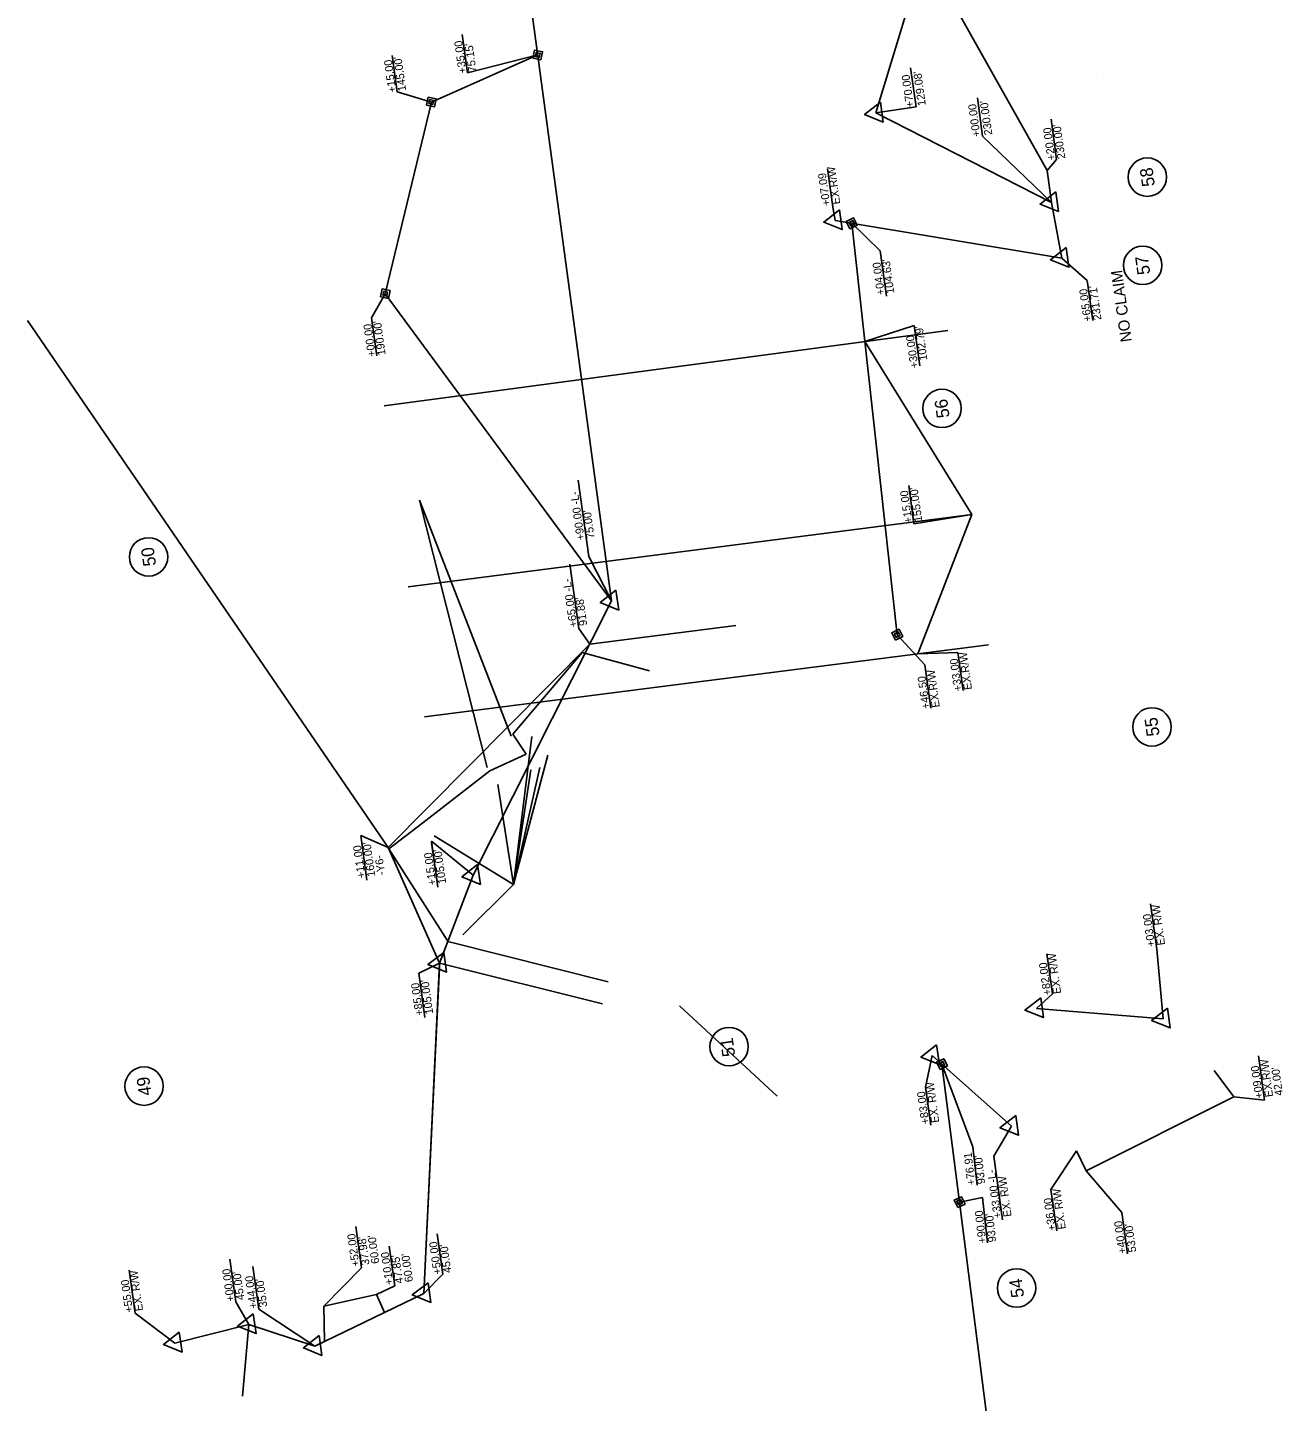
# Model space of a CAD drawing. Extents: x 474184 to 481900, y 489262 to 505659.
# Drawn here: x 477622 to 478406, y 497189 to 498047 of the extents above; entities that cross this region are included whole.
import ezdxf

# ---------------------------------------------------------------- set-up
doc = ezdxf.new("R2010")
doc.units = 0
for name, color, linetype in [('Prop Drainage Structure Box Number Symbol CELL', 7, 'Continuous'), ('Prop Drainage Structure Drop Inlet Grate 2 Wide Slots and Sag Grates 840 22 CELL', 7, 'Continuous'), ('Prop Drainage Structure Outlet Berm Ditch 850 10 Label', 7, 'Continuous'), ('Prop Drainage Structure Pipe CSP 15in', 7, 'Continuous'), ('Prop Drainage Structure Pipe Plug CELL', 7, 'Continuous'), ('Prop Drainage Structure Pipe RCP 18in Class IV', 7, 'Continuous'), ('Prop Drainage Structure Pipe RCP 18in Class IV Label', 7, 'Continuous'), ('Prop Drainage Structure Pipe Side Drain 15in Label', 7, 'Continuous'), ('Prop Drainage Structure Pipe Stub Out CELL', 7, 'Continuous'), ('Prop Drainage Structure Plot Symbol 50 Scale', 7, 'Continuous'), ('Prop Earthen Structure Base Ditch Lateral Detail Label', 7, 'Continuous'), ('Prop Earthen Structure False Sump CELL', 7, 'Continuous'), ('Prop Earthen Structure False Sump Label', 7, 'Continuous'), ('Sheet Block Title CELL', 7, 'Continuous'), ('Sheet Plot Border Outside CELL', 7, 'Continuous')]:
    doc.layers.add(name, color=color, linetype=linetype)

msp = doc.modelspace()

# ---------------------------------------------------------------- linework, layer by layer
at = {"layer": 'Prop Drainage Structure Box Number Symbol CELL'}
msp.add_line((478090.16, 497379.52), (478029.28, 497436.03), dxfattribs=at)
at = {"layer": 'Prop Drainage Structure Drop Inlet Grate 2 Wide Slots and Sag Grates 840 22 CELL'}
for p, q in [((477874.31, 498000.53), (477940.73, 498029.97)), ((477845.49, 497880.8), (477874.31, 498000.53)), ((477986.87, 497688.92), (477845.49, 497880.8))]:
    msp.add_line(p, q, dxfattribs=at)
at = {"layer": 'Prop Drainage Structure Outlet Berm Ditch 850 10 Label'}
for p, q in [((478165.24, 497667.84), (478136.84, 497924.8)), ((478204.16, 497313.42), (478193.15, 497399.62)), ((478260.5, 496872), (478204.16, 497313.42))]:
    msp.add_line(p, q, dxfattribs=at)
at = {"layer": 'Prop Drainage Structure Pipe CSP 15in'}
for p, q in [((478321.41, 497953.63), (478321.41, 497953.63)), ((478318.52, 497898.55), (478318.52, 497898.55)), ((478193.19, 497809.15), (478193.19, 497809.15)), ((477697.68, 497716.44), (477697.68, 497716.44)), ((478324.33, 497610.23), (478324.33, 497610.23)), ((478060.24, 497410.58), (478060.24, 497410.58)), ((477694.87, 497385.86), (477694.87, 497385.86)), ((478239.77, 497259.78), (478239.77, 497259.78))]:
    msp.add_line(p, q, dxfattribs=at)
for centre in [(478321.41, 497953.63), (478318.52, 497898.55), (478193.19, 497809.15), (477697.68, 497716.44), (478324.33, 497610.23), (478060.24, 497410.58), (477694.87, 497385.86), (478239.77, 497259.78)]:
    msp.add_circle(centre, 12, dxfattribs=at)
at = {"layer": 'Prop Drainage Structure Pipe RCP 18in Class IV'}
for p, q in [((477940.73, 498029.97), (477940.73, 498029.97)), ((477874.31, 498000.53), (477874.31, 498000.53)), ((478151.97, 497993.74), (478151.97, 497993.74)), ((478261.6, 497937.84), (478261.6, 497937.84)), ((478126.49, 497926.51), (478126.49, 497926.51)), ((478136.84, 497924.8), (478136.84, 497924.8)), ((478268.07, 497903.03), (478268.07, 497903.03)), ((477845.49, 497880.8), (477845.49, 497880.8)), ((477986.86, 497688.92), (477986.86, 497688.92)), ((478165.24, 497667.84), (478165.24, 497667.84)), ((477900.49, 497517.57), (477900.49, 497517.57)), ((477879.32, 497462.76), (477879.32, 497462.76)), ((478252.13, 497434.35), (478252.13, 497434.35)), ((478331.24, 497427.91), (478331.24, 497427.91)), ((478187.13, 497405), (478187.13, 497405)), ((478193.15, 497399.62), (478193.15, 497399.62)), ((478236.53, 497360.9), (478236.53, 497360.9)), ((478204.16, 497313.42), (478204.16, 497313.42)), ((477869.55, 497256.44), (477869.55, 497256.44)), ((477760.36, 497236.95), (477760.36, 497236.95)), ((477714.16, 497225.41), (477714.16, 497225.41)), ((477801.51, 497223.4), (477801.51, 497223.4))]:
    msp.add_line(p, q, dxfattribs=at)
for points in [[(478154.69, 498000.42), (478156.4, 497988.06), (478144.83, 497992.73)], [(478264.31, 497944.53), (478266.03, 497932.17), (478254.45, 497936.84)], [(478129.21, 497933.2), (478130.92, 497920.84), (478119.35, 497925.51)], [(478270.78, 497909.71), (478272.5, 497897.35), (478260.93, 497902.02)], [(477989.57, 497695.61), (477991.29, 497683.25), (477979.72, 497687.92)], [(477903.2, 497524.26), (477904.92, 497511.9), (477893.35, 497516.57)], [(477882.03, 497469.44), (477883.75, 497457.08), (477872.18, 497461.75)], [(478254.84, 497441.03), (478256.56, 497428.67), (478244.98, 497433.35)], [(478333.96, 497434.6), (478335.67, 497422.24), (478324.1, 497426.91)], [(478189.84, 497411.68), (478191.56, 497399.32), (478179.99, 497403.99)], [(478239.25, 497367.58), (478240.96, 497355.22), (478229.39, 497359.89)], [(477872.27, 497263.12), (477873.98, 497250.76), (477862.41, 497255.43)], [(477763.07, 497243.64), (477764.79, 497231.28), (477753.22, 497235.95)], [(477716.87, 497232.1), (477718.58, 497219.74), (477707.01, 497224.41)], [(477804.23, 497230.08), (477805.94, 497217.72), (477794.37, 497222.39)]]:
    msp.add_lwpolyline(points, close=True, dxfattribs=at)
at = {"layer": 'Prop Drainage Structure Pipe RCP 18in Class IV Label'}
for points in [[(477937.7, 498028.02), (477938.79, 498033), (477943.76, 498031.91), (477942.68, 498026.94)], [(477939.22, 498028.99), (477939.76, 498031.48), (477942.25, 498030.94), (477941.7, 498028.45)], [(477871.28, 497998.59), (477872.36, 498003.56), (477877.34, 498002.47), (477876.25, 497997.5)], [(477872.79, 497999.56), (477873.33, 498002.04), (477875.82, 498001.5), (477875.28, 497999.01)], [(478135.67, 497921.39), (478133.43, 497925.97), (478138.01, 497928.2), (478140.24, 497923.63)], [(478136.25, 497923.1), (478135.14, 497925.38), (478137.42, 497926.5), (478138.54, 497924.21)], [(477842.46, 497878.86), (477843.54, 497883.83), (477848.52, 497882.75), (477847.43, 497877.77)], [(477843.97, 497879.83), (477844.52, 497882.32), (477847, 497881.78), (477846.46, 497879.29)], [(478164.07, 497664.44), (478161.84, 497669.01), (478166.41, 497671.24), (478168.65, 497666.67)], [(478164.66, 497666.14), (478163.54, 497668.43), (478165.83, 497669.54), (478166.94, 497667.26)], [(478191.98, 497396.22), (478189.75, 497400.79), (478194.32, 497403.02), (478196.56, 497398.45)], [(478192.57, 497397.92), (478191.45, 497400.21), (478193.74, 497401.32), (478194.85, 497399.04)], [(478202.98, 497310.01), (478200.75, 497314.59), (478205.33, 497316.82), (478207.56, 497312.24)], [(478203.57, 497311.71), (478202.45, 497314), (478204.74, 497315.12), (478205.86, 497312.83)]]:
    msp.add_lwpolyline(points, close=True, dxfattribs=at)
at = {"layer": 'Prop Drainage Structure Pipe Side Drain 15in Label'}
for p, q in [((478151.97, 497993.74), (478182.38, 498093.88)), ((477986.86, 497688.92), (477935.51, 498068.61)), ((478261.6, 497937.84), (478151.97, 497993.74)), ((478268.07, 497903.03), (478261.6, 497937.84)), ((478268.07, 497903.03), (478126.49, 497926.51)), ((477900.49, 497517.57), (477986.86, 497688.92)), ((477879.32, 497462.76), (477900.49, 497517.57)), ((477869.55, 497256.44), (477879.32, 497462.76)), ((478331.24, 497427.91), (478252.13, 497434.35)), ((478236.53, 497360.9), (478187.13, 497405)), ((477801.51, 497223.4), (477869.55, 497256.44)), ((477714.16, 497225.41), (477760.36, 497236.95)), ((477760.36, 497236.95), (477801.51, 497223.4))]:
    msp.add_line(p, q, dxfattribs=at)
at = {"layer": 'Prop Drainage Structure Pipe Stub Out CELL'}
for p, q in [((478258.84, 497957.86), (478182.38, 498093.88)), ((478293.82, 498017.59), (478293.82, 498017.59)), ((478261.6, 497937.84), (478258.84, 497957.86)), ((478211.82, 497742.98), (478145.01, 497850.88)), ((478178.17, 497655.88), (478211.82, 497742.98)), ((477847.3, 497534.87), (477973.28, 497661.99)), ((477879.32, 497462.76), (477847.3, 497534.87)), ((478363.15, 497395.66), (478375.46, 497379.21)), ((478283.3, 497333.07), (478375.46, 497379.21)), ((478283.3, 497333.07), (478277.26, 497345.54)), ((477807.13, 497248.34), (477840.11, 497255.64)), ((477845.04, 497244.53), (477840.11, 497255.64)), ((477807.53, 497226.32), (477807.13, 497248.34))]:
    msp.add_line(p, q, dxfattribs=at)
at = {"layer": 'Prop Drainage Structure Plot Symbol 50 Scale'}
for p, q in [((478173.61, 498021.96), (478177.01, 497997.54)), ((478215.27, 498003.15), (478218.59, 497979.24)), ((478121.74, 497958.86), (478125.24, 497933.7)), ((478268.07, 497903.03), (478283.83, 497889.15)), ((478283.83, 497889.15), (478287.33, 497863.99)), ((477965.99, 497764.27), (477972.6, 497716.78)), ((477986.86, 497688.92), (477972.6, 497716.78)), ((477874.31, 497538.97), (477878.32, 497510.14)), ((477874.31, 497538.97), (477900.49, 497517.57)), ((477874.46, 497537.88), (477878.32, 497510.14)), ((478323.35, 497499.75), (478327.28, 497471.51)), ((478258.74, 497468.46), (478262.2, 497443.58)), ((477866.39, 497456.45), (477879.32, 497462.76)), ((477866.39, 497456.45), (477870.25, 497428.71)), ((477866.39, 497456.45), (477870.25, 497428.71)), ((478182.97, 497385.32), (478186.28, 497361.5)), ((478225.55, 497342.13), (478236.53, 497360.9)), ((478225.55, 497342.13), (478231.08, 497302.4)), ((477877.86, 497293.65), (477881.37, 497268.47)), ((477748.47, 497277.7), (477752.18, 497251.05)), ((477685.51, 497271), (477689.27, 497244.01)), ((477762.74, 497273.3), (477766.45, 497246.65)), ((477881.37, 497268.47), (477869.55, 497256.44)), ((477760.36, 497236.95), (477752.18, 497251.05)), ((477801.51, 497223.4), (477766.45, 497246.65))]:
    msp.add_line(p, q, dxfattribs=at)
for points in [[(478177.01, 497997.54), (478151.97, 497993.74)], [(478218.59, 497979.24), (478261.6, 497937.84)], [(478125.24, 497933.7), (478126.49, 497926.51)], [(478327.28, 497471.51), (478331.24, 497427.91)], [(478262.2, 497443.58), (478252.13, 497434.35)], [(478182.97, 497385.32), (478187.13, 497405)], [(477689.27, 497244.01), (477714.16, 497225.41)]]:
    msp.add_lwpolyline(points, dxfattribs=at)
at = {"layer": 'Prop Earthen Structure Base Ditch Lateral Detail Label'}
for p, q in [((478154.53, 497907.54), (478136.84, 497924.8)), ((478154.53, 497907.54), (478158.46, 497879.29)), ((478182.48, 497649.08), (478165.24, 497667.84)), ((478182.48, 497649.08), (478186.27, 497621.88)), ((478193.15, 497399.62), (478212.35, 497347.93)), ((478212.35, 497347.93), (478215.1, 497324.04)), ((478204.16, 497313.42), (478218.41, 497316.35)), ((478218.41, 497316.35), (478221.68, 497287.96))]:
    msp.add_line(p, q, dxfattribs=at)
at = {"layer": 'Prop Earthen Structure False Sump CELL'}
for p, q in [((477893.61, 498042.64), (477896.92, 498018.82)), ((477849.87, 498029.55), (477853.02, 498006.92)), ((477836.89, 497865.76), (477840.21, 497841.94))]:
    msp.add_line(p, q, dxfattribs=at)
for points in [[(477896.92, 498018.82), (477940.73, 498029.97)], [(477853.02, 498006.92), (477874.31, 498000.53)], [(477836.89, 497865.76), (477845.49, 497880.8)]]:
    msp.add_lwpolyline(points, dxfattribs=at)
at = {"layer": 'Prop Earthen Structure False Sump Label'}
for p, q in [((478261.28, 497989.83), (478264.78, 497964.72)), ((478258.84, 497957.86), (478264.78, 497964.72)), ((478175.84, 497860.97), (478179.35, 497835.77)), ((478172.39, 497760.97), (478175.7, 497737.13)), ((477960.75, 497711.92), (477966.34, 497671.78)), ((477973.28, 497661.99), (477966.34, 497671.78)), ((478203.13, 497656.77), (478206.44, 497632.95)), ((477830.2, 497542.35), (477834.06, 497514.6)), ((477830.2, 497542.35), (477834.06, 497514.6)), ((477830.2, 497542.35), (477847.3, 497534.87)), ((478390.81, 497404.71), (478394.66, 497377.05)), ((478261.2, 497321.41), (478264.81, 497295.52)), ((478305.48, 497306.92), (478309.08, 497281.04)), ((477827.03, 497298.22), (477830.63, 497272.35)), ((477848, 497285.99), (477851.47, 497261.1)), ((477807.13, 497248.34), (477830.63, 497272.35)), ((477851.47, 497261.1), (477840.11, 497255.64))]:
    msp.add_line(p, q, dxfattribs=at)
for points in [[(478175.84, 497860.97), (478145.01, 497850.88)], [(478175.7, 497737.13), (478211.82, 497742.98)], [(478203.13, 497656.77), (478178.17, 497655.88)], [(478394.66, 497377.05), (478375.46, 497379.21)], [(478261.2, 497321.41), (478277.26, 497345.54)], [(478305.48, 497306.92), (478283.3, 497333.07)]]:
    msp.add_lwpolyline(points, dxfattribs=at)
at = {"layer": 'Sheet Block Title CELL'}
msp.add_line((477869.55, 497256.44), (477879.53, 497464.17), dxfattribs=at)
at = {"layer": 'Sheet Plot Border Outside CELL'}
for p, q in [((477847.3, 497534.87), (477622.07, 497864.13)), ((477844.89, 497810.71), (478196.75, 497857.8)), ((477909.12, 497584.92), (477866.83, 497751.88)), ((477924.06, 497604.46), (477866.83, 497751.88)), ((477859.71, 497697.72), (478211.82, 497742.98)), ((477973.28, 497661.99), (478064.42, 497673.62)), ((477847.3, 497534.87), (477973.15, 497661.72)), ((477870.08, 497616.55), (478222.22, 497661.51)), ((477925.25, 497605.79), (477968.54, 497656.77)), ((478010.5, 497645.25), (477968.54, 497656.77)), ((477933.48, 497593.13), (477925.25, 497605.79)), ((477937.11, 497604.29), (477925.61, 497511.71)), ((477910.75, 497582.73), (477933.48, 497593.13)), ((477947.07, 497592.63), (477925.61, 497511.71)), ((477868.91, 497550.35), (477910.75, 497582.73)), ((477942.12, 497584.93), (477925.61, 497511.71)), ((477936.5, 497583.43), (477925.61, 497511.71)), ((477915.85, 497574.18), (477925.61, 497511.71)), ((477875.96, 497542.19), (477925.61, 497511.71)), ((477893.88, 497480.44), (477925.61, 497511.71)), ((477884.5, 497476.18), (477984.64, 497451.05)), ((477879.32, 497462.76), (477981.16, 497437.2)), ((477760.36, 497236.95), (477756.37, 497192.13))]:
    msp.add_line(p, q, dxfattribs=at)
msp.add_lwpolyline([(477884.59, 497476.4), (477847.68, 497534.07), (477868.95, 497550.38)], dxfattribs=at)

# ---------------------------------------------------------------- texts
at = {"layer": 'Prop Drainage Structure Pipe CSP 15in'}
for s, p in [('58', (478326.2, 497948.27)), ('57', (478323.3, 497893.19)), ('56', (478197.99, 497803.72)), ('50', (477702.45, 497711.14)), ('55', (478329.12, 497604.88)), ('51', (478064.1, 497404.76)), ('49', (477699.66, 497380.43)), ('54', (478244.57, 497254.3))]:
    msp.add_text(s, height=8, rotation=97.92268, dxfattribs=at).set_placement(p)
at = {"layer": 'Prop Drainage Structure Pipe Plug CELL'}
msp.add_text('NO CLAIM', height=7, rotation=97.92268, dxfattribs=at).set_placement((478311.79, 497851.12))
at = {"layer": 'Prop Drainage Structure Plot Symbol 50 Scale'}
for s, p in [('+70.00', (478175.7, 497997.49)), ("129.08'", (478183.13, 497998.52)), ('+00.00', (478217.24, 497979.18)), ("230.00'", (478224.67, 497980.21)), ('+07.09', (478123.46, 497936.07)), ('EX.R/W', (478129.65, 497936.93)), ('+65.00', (478286.61, 497863.76)), ("231.71'", (478292.8, 497864.62)), ('+90.00 -L-', (477970.08, 497727.24)), ("75.00'", (477976.27, 497728.1)), ('+15.00', (477877.39, 497511.7)), ("105.00'", (477883.58, 497512.56)), ('+03.00', (478326.34, 497473.31)), ('EX. R/W', (478332.53, 497474.18)), ('EX. R/W', (478267.64, 497443.82)), ('+82.00 ', (478261.45, 497442.96)), ('+85.00', (477869.31, 497430.27)), ("105.00'", (477875.5, 497431.13)), ('+83.00', (478185.29, 497362.44)), ('EX. R/W', (478191.48, 497363.31)), ('+33.00 -L- ', (478230.49, 497303.7)), ('EX. R/W', (478236.68, 497304.56)), ('+50.00', (477880.64, 497268.63)), ("45.00'", (477886.83, 497269.49)), ('EX. R/W', (477694.25, 497245.71)), ('+00.00', (477751.39, 497251.68)), ("45.00'", (477757.58, 497252.54)), ('+55.00', (477688.06, 497244.85)), ('+44.00', (477765.66, 497247.28)), ("35.00'", (477771.85, 497248.14))]:
    msp.add_text(s, height=5, rotation=97.92268, dxfattribs=at).set_placement(p)
at = {"layer": 'Prop Earthen Structure Base Ditch Lateral Detail Label'}
for s, rotation, p in [('+04.00', 97.92268, (478157.51, 497880.35)), ("104.63' ", 97.92268, (478163.45, 497881.18)), ('+46.50', 97.92268, (478185.65, 497621.8)), ('EX.R/W ', 97.92268, (478191.84, 497622.66)), ('+76.91', 96.56297, (478214.02, 497324.22)), ("93.00'", 96.56297, (478220.23, 497324.94)), ('+90.00', 96.56297, (478220.89, 497287.96)), ("93.00'", 96.56297, (478227.1, 497288.68))]:
    msp.add_text(s, height=5, rotation=rotation, dxfattribs=at).set_placement(p)
at = {"layer": 'Prop Earthen Structure False Sump CELL'}
for s, p in [('+35.00', (477896.31, 498018.74)), ("75.15'", (477902.5, 498019.6)), ('+15.00', (477852.4, 498006.83)), ("145.00'", (477858.59, 498007.69)), ('+00.00', (477839.59, 497841.85)), ("190.00'", (477845.78, 497842.72))]:
    msp.add_text(s, height=5, rotation=97.92268, dxfattribs=at).set_placement(p)
at = {"layer": 'Prop Earthen Structure False Sump Label'}
for s, rotation, p in [('+20.00', 97.92268, (478264.05, 497964.5)), ("230.00'", 97.92268, (478270.24, 497965.36)), ('+30.00', 97.92268, (478178.46, 497834.68)), ("102.79'", 97.92268, (478184.1, 497839.46)), ('+15.00', 97.92268, (478174.72, 497737.8)), ("155.00'", 97.92268, (478180.91, 497738.67)), ('+65.00 -L-', 97.92268, (477965.47, 497672.87)), ("91.88'", 97.92268, (477971.66, 497673.74)), ('EX.R/W', 97.92268, (478211.94, 497633.72)), ('+33.00', 97.92268, (478205.75, 497632.86)), ('+11.00', 97.92268, (477833.12, 497516.16)), ("160.00'", 97.92268, (477839.31, 497517.02)), ('-Y6-', 97.92268, (477845.5, 497517.88)), ('+09.00', 97.92268, (478393.79, 497378.51)), ('EX.R/W', 97.92268, (478399.98, 497379.38)), ("42.00'", 97.92268, (478406.17, 497380.24)), ('EX. R/W', 97.78921, (478270.54, 497296.74)), ('+36.00 ', 97.78921, (478264.35, 497295.89)), ('+40.00 ', 97.78921, (478308.37, 497281.56)), ("53.00'", 97.78921, (478314.56, 497282.41)), ('+52.00', 97.92268, (477829.49, 497273.57)), ("37.98'", 97.92268, (477835.68, 497274.43)), ("60.00'", 97.92268, (477841.87, 497275.29)), ('+10.00', 97.92268, (477850.47, 497262.12)), ("47.85'", 97.92268, (477856.66, 497262.98)), ("60.00'", 97.92268, (477862.85, 497263.84))]:
    msp.add_text(s, height=5, rotation=rotation, dxfattribs=at).set_placement(p)

doc.saveas('drawing.dxf')
